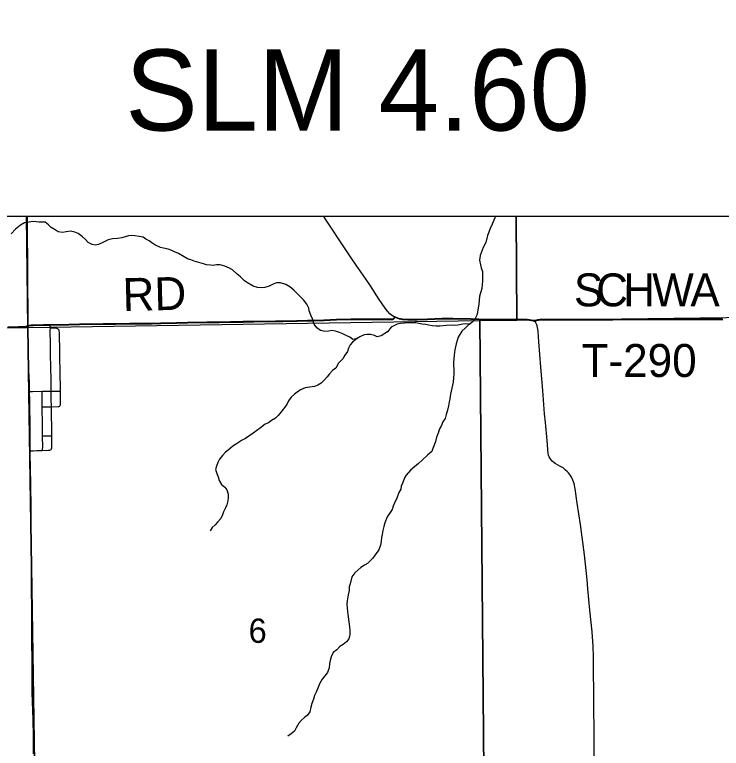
# Model space of a CAD drawing. Extents: x 0 to 34, y 0 to 22.
# Drawn here: x 3.608 to 4.826, y 17.663 to 18.929 of the extents above; entities that cross this region are included whole.
import ezdxf

# ---------------------------------------------------------------- set-up
doc = ezdxf.new("R2010")
doc.units = 0
for name, color, linetype in [('Default', 7, 'Continuous'), ('GM_X_County_Road', 7, 'Continuous'), ('GM_X_Minor_River', 7, 'Continuous'), ('GM_X_Section', 7, 'Continuous'), ('GM_X_Section_Text', 7, 'Continuous'), ('GM_X_Township_Road', 7, 'Continuous'), ('GM_X_Township_Road_Text', 7, 'Continuous'), ('SH_Text', 7, 'Continuous')]:
    doc.layers.add(name, color=color, linetype=linetype)

msp = doc.modelspace()

# ---------------------------------------------------------------- linework, layer by layer
at = {"layer": 'Default'}
for points in [[(4.8287, 18.4036), (4.7759, 18.4035), (4.7231, 18.4033), (4.6858, 18.4035), (4.639, 18.4032), (4.6202, 18.4032), (4.5708, 18.403), (4.5304, 18.403), (4.518, 18.4029), (4.5135, 18.4029), (4.5111, 18.4027), (4.5092, 18.4023), (4.5078, 18.4019), (4.5065, 18.4013), (4.5043, 18.3999), (4.5016, 18.4012), (4.4986, 18.4021), (4.4955, 18.4026), (4.4914, 18.4029), (4.475, 18.4028), (4.4408, 18.4028), (4.4222, 18.403), (4.3942, 18.404), (4.3631, 18.4046), (4.3445, 18.4045), (4.3196, 18.4037), (4.301, 18.4031), (4.2855, 18.4032), (4.2763, 18.4037), (4.2733, 18.4042), (4.2703, 18.4048), (4.2675, 18.4057), (4.2647, 18.4069), (4.2635, 18.4075), (4.262, 18.4054), (4.2613, 18.4045), (4.2607, 18.4041), (4.2596, 18.4037), (4.2574, 18.4035), (4.2496, 18.4034), (4.231, 18.4036), (4.2029, 18.4037), (4.1876, 18.4035), (4.1628, 18.4028), (4.1411, 18.402), (4.1223, 18.4015), (4.1128, 18.4015), (4.0946, 18.4009), (4.0699, 18.4003), (4.0574, 18.4), (4.0452, 18.3998), (4.0201, 18.3994), (4.0016, 18.3993), (3.9799, 18.399), (3.9609, 18.3986), (3.9391, 18.3983), (3.9058, 18.3979), (3.8871, 18.3974), (3.8593, 18.3968), (3.8435, 18.3963), (3.8066, 18.3959), (3.7815, 18.3956), (3.7601, 18.3953), (3.7196, 18.3948), (3.7009, 18.3944), (3.6689, 18.3939), (3.6577, 18.3937), (3.6394, 18.3933), (3.636, 18.3932), (3.6328, 18.3927), (3.6307, 18.3922), (3.6302, 18.392), (3.6272, 18.3911), (3.6239, 18.3906), (3.6146, 18.3902), (3.5959, 18.3898)], [(3.5959, 18.3898), (3.6146, 18.3902), (3.6239, 18.3906), (3.6272, 18.3911), (3.6302, 18.392), (3.6307, 18.3922), (3.6328, 18.3927), (3.636, 18.3932), (3.6394, 18.3933), (3.6577, 18.3937), (3.6689, 18.3939), (3.7009, 18.3944), (3.7196, 18.3948), (3.7601, 18.3953), (3.7815, 18.3956), (3.8066, 18.3959), (3.8435, 18.3963), (3.8593, 18.3968), (3.8871, 18.3974), (3.9058, 18.3979), (3.9391, 18.3983), (3.9609, 18.3986), (3.9799, 18.399), (4.0016, 18.3993), (4.0201, 18.3994), (4.0452, 18.3998), (4.0574, 18.4), (4.0699, 18.4003), (4.0946, 18.4009), (4.1128, 18.4015), (4.1223, 18.4015), (4.1411, 18.402), (4.1628, 18.4028), (4.1876, 18.4035), (4.2029, 18.4037), (4.231, 18.4036), (4.2496, 18.4034), (4.2574, 18.4035), (4.2596, 18.4037), (4.2607, 18.4041), (4.2613, 18.4045), (4.262, 18.4054), (4.2635, 18.4075), (4.2647, 18.4069), (4.2675, 18.4057), (4.2703, 18.4048), (4.2733, 18.4042), (4.2763, 18.4037), (4.2855, 18.4032), (4.301, 18.4031), (4.3196, 18.4037), (4.3445, 18.4045), (4.3631, 18.4046), (4.3942, 18.404), (4.4222, 18.403), (4.4408, 18.4028), (4.475, 18.4028), (4.4914, 18.4029), (4.4955, 18.4026), (4.4986, 18.4021), (4.5016, 18.4012), (4.5043, 18.3999), (4.5065, 18.4013), (4.5078, 18.4019), (4.5092, 18.4023), (4.5111, 18.4027), (4.5135, 18.4029), (4.518, 18.4029), (4.5304, 18.403), (4.5708, 18.403), (4.6202, 18.4032), (4.639, 18.4032), (4.6858, 18.4035), (4.7231, 18.4033), (4.7759, 18.4035), (4.8287, 18.4036)]]:
    msp.add_lwpolyline(points, dxfattribs=at)
at = {"layer": 'GM_X_County_Road'}
for points in [[(3.6309, 18.3916), (3.6308, 18.4178), (3.6306, 18.4613), (3.6302, 18.5078), (3.63, 18.5451), (3.6297, 18.5699), (3.6297, 18.5805)], [(4.2637, 18.4069), (4.2622, 18.4077), (4.2596, 18.4093), (4.2572, 18.4111), (4.2549, 18.413), (4.2507, 18.4174), (4.2467, 18.4224), (4.2362, 18.4377), (4.2211, 18.4609), (4.2125, 18.4738), (4.1968, 18.4968), (4.1881, 18.5095), (4.1778, 18.5249), (4.145, 18.5744), (4.1409, 18.5805)], [(4.5045, 18.3994), (4.5018, 18.4007), (4.4988, 18.4015), (4.4957, 18.402), (4.4916, 18.4024), (4.4752, 18.4023), (4.441, 18.4022), (4.4224, 18.4025), (4.3945, 18.4035), (4.3634, 18.4041), (4.3447, 18.404), (4.3198, 18.4031), (4.3012, 18.4025), (4.2857, 18.4027), (4.2765, 18.4032), (4.2735, 18.4036), (4.2706, 18.4043), (4.2677, 18.4052), (4.2649, 18.4063), (4.2637, 18.4069)], [(4.6069, 17.6467), (4.6071, 17.6716), (4.6069, 17.6964), (4.6065, 17.7306), (4.6064, 17.7586), (4.6061, 17.7975), (4.6057, 17.821), (4.6052, 17.8393), (4.6035, 17.8641), (4.5999, 17.9012), (4.5964, 17.9383), (4.5948, 17.9536), (4.5902, 17.9969), (4.5865, 18.0277), (4.5836, 18.0493), (4.578, 18.0861), (4.5742, 18.1107), (4.5725, 18.12), (4.5705, 18.1256), (4.5694, 18.1284), (4.5681, 18.1312), (4.5665, 18.1337), (4.5645, 18.1363), (4.5629, 18.1383), (4.5607, 18.1407), (4.5578, 18.1433), (4.5534, 18.1469), (4.5481, 18.1501), (4.54, 18.1548), (4.5373, 18.1563), (4.5346, 18.1586), (4.5332, 18.1606), (4.5312, 18.1632), (4.5296, 18.166), (4.5285, 18.1692), (4.528, 18.1722), (4.5272, 18.1789), (4.5259, 18.194), (4.5232, 18.2254), (4.5217, 18.2402), (4.5185, 18.2805), (4.5151, 18.3208), (4.5118, 18.3642), (4.5103, 18.3827), (4.5095, 18.3893), (4.5089, 18.392), (4.5082, 18.3941), (4.5072, 18.3963), (4.5058, 18.3982), (4.5045, 18.3994)], [(3.6344, 18.1766), (3.6342, 18.2128), (3.6337, 18.2626), (3.6334, 18.2787), (3.6333, 18.2936), (3.6323, 18.3153), (3.6313, 18.337), (3.6309, 18.3557), (3.631, 18.3899), (3.6309, 18.3916)], [(3.6404, 17.6536), (3.64, 17.6845), (3.6395, 17.7129), (3.6381, 17.7592), (3.6381, 17.784), (3.6378, 17.8089), (3.6373, 17.8524), (3.6373, 17.8959), (3.637, 17.9456), (3.6369, 17.986), (3.6362, 18.0357), (3.636, 18.0761), (3.6354, 18.1196), (3.6344, 18.1724), (3.6344, 18.1766)]]:
    msp.add_lwpolyline(points, dxfattribs=at)
at = {"layer": 'GM_X_Minor_River'}
for points in [[(4.2016, 18.3723), (4.196, 18.3697), (4.191, 18.3686), (4.1857, 18.3724), (4.1792, 18.3754), (4.1734, 18.3781), (4.1677, 18.3804), (4.1608, 18.3827), (4.1547, 18.3838), (4.1494, 18.3831), (4.1425, 18.3823), (4.1349, 18.3842), (4.1288, 18.3884), (4.1245, 18.3949), (4.1211, 18.404), (4.1184, 18.4105), (4.1157, 18.4177), (4.1149, 18.4226), (4.1115, 18.4295), (4.1061, 18.4367), (4.1012, 18.4413), (4.0954, 18.4474), (4.0889, 18.4538), (4.0824, 18.4595), (4.0751, 18.4633), (4.066, 18.466), (4.0591, 18.466), (4.0538, 18.4637), (4.0469, 18.4603), (4.0393, 18.458), (4.0332, 18.4577), (4.0263, 18.4584), (4.0191, 18.4607), (4.0095, 18.4664), (4.0041, 18.4695), (3.9969, 18.4767), (3.9915, 18.4812), (3.9835, 18.4885), (3.9781, 18.4915), (3.9701, 18.4953), (3.9621, 18.4976), (3.9556, 18.4972), (3.9503, 18.4961), (3.9453, 18.4965), (3.9388, 18.4972), (3.9335, 18.4988), (3.9251, 18.5014), (3.9171, 18.5037), (3.9113, 18.506), (3.906, 18.5075), (3.8999, 18.5113), (3.8903, 18.5167), (3.8834, 18.5197), (3.8785, 18.522), (3.8727, 18.5243), (3.8643, 18.5262), (3.8594, 18.5273), (3.8494, 18.5319), (3.8445, 18.5353), (3.8395, 18.5388), (3.8342, 18.5418), (3.8292, 18.5448), (3.8223, 18.5464), (3.8147, 18.5471), (3.8097, 18.5479), (3.804, 18.5475), (3.7926, 18.5437), (3.7853, 18.543), (3.7765, 18.5422), (3.7689, 18.5407), (3.7609, 18.5365), (3.7525, 18.5327), (3.7468, 18.5312), (3.7411, 18.5323), (3.7346, 18.5361), (3.7296, 18.5411), (3.7239, 18.546), (3.717, 18.5514), (3.7112, 18.5536), (3.704, 18.5552), (3.6964, 18.5544), (3.6903, 18.5533), (3.6826, 18.5544), (3.6773, 18.5579), (3.6708, 18.562), (3.6658, 18.5666), (3.6604, 18.5708), (3.6555, 18.5712), (3.6498, 18.5712), (3.6448, 18.5716), (3.6387, 18.5719), (3.6326, 18.5712), (3.6246, 18.5697), (3.6177, 18.5655), (3.6093, 18.5586), (3.6017, 18.5507)], [(4.4368, 18.5805), (4.4359, 18.5784), (4.431, 18.5673), (4.4279, 18.5601), (4.4256, 18.5536), (4.4234, 18.5479), (4.4203, 18.5358), (4.4158, 18.527), (4.4105, 18.5137), (4.4094, 18.5054), (4.4109, 18.4974), (4.4124, 18.4921), (4.4147, 18.4856), (4.4148, 18.4768), (4.4148, 18.4692), (4.414, 18.4635), (4.4133, 18.4567), (4.4114, 18.451), (4.4091, 18.443), (4.4088, 18.4358), (4.408, 18.4297), (4.4073, 18.4232), (4.4061, 18.4156), (4.4046, 18.4103), (4.4012, 18.4038), (4.3963, 18.3981), (4.3898, 18.3932), (4.3844, 18.3883), (4.3791, 18.3829), (4.3727, 18.3727), (4.3689, 18.3613), (4.3666, 18.3506), (4.3655, 18.3415), (4.3644, 18.3286), (4.3644, 18.3229), (4.3652, 18.3179), (4.3652, 18.3092), (4.3644, 18.3023), (4.3637, 18.2951), (4.3618, 18.2848)], [(4.394, 18.3947), (4.3856, 18.3955), (4.3806, 18.3951), (4.3718, 18.3932), (4.3661, 18.3928), (4.3612, 18.3932), (4.3524, 18.3925), (4.3409, 18.3917), (4.3344, 18.3917), (4.3276, 18.3921), (4.3215, 18.3932), (4.3165, 18.3944), (4.3104, 18.3951), (4.305, 18.3963), (4.2993, 18.397), (4.2925, 18.397), (4.2867, 18.3974), (4.273, 18.3959), (4.2673, 18.3948), (4.257, 18.3898), (4.2505, 18.3815), (4.2398, 18.375), (4.233, 18.3731), (4.228, 18.3754), (4.2215, 18.3773), (4.2158, 18.3769), (4.2105, 18.3766), (4.2028, 18.3731), (4.196, 18.3686), (4.1903, 18.364), (4.1861, 18.3591), (4.1834, 18.3534), (4.1815, 18.3477), (4.1773, 18.3412), (4.1735, 18.3351), (4.1663, 18.3275), (4.1614, 18.3192), (4.156, 18.315), (4.1507, 18.3093), (4.1465, 18.304), (4.1419, 18.299), (4.1362, 18.2933), (4.1305, 18.2895), (4.1248, 18.2876), (4.1168, 18.2861), (4.1088, 18.285), (4.1004, 18.2816), (4.0951, 18.2778), (4.0901, 18.274), (4.0848, 18.269), (4.0798, 18.2626), (4.0772, 18.2561), (4.0673, 18.2439), (4.0623, 18.2371), (4.0574, 18.2329), (4.0509, 18.2287), (4.0456, 18.2245), (4.0399, 18.2223), (4.0315, 18.2162), (4.0254, 18.2116), (4.0193, 18.2067), (4.0056, 18.1976), (3.9991, 18.1941), (3.9903, 18.1884), (3.9838, 18.1843), (3.9762, 18.1774), (3.9713, 18.174), (3.9659, 18.1683), (3.961, 18.1618), (3.958, 18.1561), (3.9557, 18.1501), (3.9538, 18.144), (3.9561, 18.1375), (3.9588, 18.1314), (3.9603, 18.1253), (3.9642, 18.1185), (3.9703, 18.1139), (3.9737, 18.109), (3.976, 18.1018), (3.976, 18.096), (3.9753, 18.0903), (3.9734, 18.0835), (3.9711, 18.0782), (3.9681, 18.0713), (3.9662, 18.066), (3.9632, 18.0599), (3.9578, 18.0535), (3.9536, 18.0485), (3.9483, 18.044), (3.9449, 18.0383)], [(4.3618, 18.2848), (4.3607, 18.2791), (4.3595, 18.2742), (4.358, 18.2662), (4.3573, 18.2609), (4.3561, 18.254), (4.3543, 18.2464), (4.352, 18.2392), (4.3501, 18.232), (4.3459, 18.2263), (4.3433, 18.2191), (4.3402, 18.2141), (4.3379, 18.2069), (4.3353, 18.2), (4.3334, 18.1924), (4.3311, 18.186), (4.3288, 18.1807), (4.327, 18.175), (4.3201, 18.1693), (4.3106, 18.1605), (4.3041, 18.1544), (4.2904, 18.143), (4.2828, 18.1347), (4.2801, 18.1297), (4.2771, 18.1217), (4.2744, 18.1153), (4.2737, 18.1103), (4.2703, 18.1046), (4.2665, 18.0929), (4.2634, 18.0879), (4.2604, 18.0811), (4.2585, 18.075), (4.2543, 18.0685), (4.2501, 18.0624), (4.246, 18.0522), (4.2441, 18.0457), (4.2429, 18.0389), (4.2414, 18.032), (4.2403, 18.0271), (4.2399, 18.0202), (4.2388, 18.0138), (4.2358, 18.0058), (4.2297, 17.9967), (4.2255, 17.991), (4.2164, 17.9818), (4.211, 17.9792), (4.2049, 17.975), (4.1946, 17.9659), (4.1893, 17.959), (4.1863, 17.9469), (4.1848, 17.9416), (4.1844, 17.9355), (4.1829, 17.9282), (4.181, 17.9176), (4.1807, 17.9115), (4.1811, 17.9054), (4.1818, 17.8993), (4.1822, 17.8944), (4.1838, 17.8815), (4.1853, 17.8727), (4.1857, 17.8659), (4.1857, 17.8594), (4.1839, 17.8522), (4.1797, 17.8469), (4.174, 17.8423), (4.1686, 17.8385), (4.1633, 17.8328), (4.1572, 17.8282), (4.1538, 17.821), (4.1519, 17.8146), (4.1508, 17.8089), (4.15, 17.802), (4.1474, 17.794), (4.1428, 17.7879), (4.1382, 17.7822), (4.1337, 17.7746), (4.1318, 17.7697), (4.1276, 17.7598), (4.1246, 17.7541), (4.123, 17.748), (4.1204, 17.7404), (4.1185, 17.734), (4.1166, 17.726), (4.1124, 17.7195), (4.1075, 17.7161), (4.1025, 17.7119), (4.0976, 17.7066), (4.0934, 17.6986), (4.0904, 17.6925), (4.0843, 17.688), (4.0789, 17.6842)]]:
    msp.add_lwpolyline(points, dxfattribs=at)
at = {"layer": 'GM_X_Section'}
for points in [[(4.4724, 18.5805), (4.4738, 18.4018), (5.4223, 18.414), (5.4724, 18.4134), (5.472, 19.4291), (4.4662, 19.4189), (4.4671, 19.2976), (5.3223, 19.2976), (5.3223, 18.5805)], [(3.619, 19.2976), (3.6177, 19.3939), (2.6269, 19.3875), (2.6434, 18.3786), (3.6306, 18.3893), (3.6281, 18.5805), (3.1024, 18.5805), (3.1024, 19.2976)], [(3.6281, 18.5805), (3.6306, 18.3893), (4.4097, 18.4011), (4.4738, 18.4018), (4.4724, 18.5805)], [(4.4738, 18.4018), (5.4223, 18.414), (5.4312, 17.3835), (4.419, 17.3654), (4.4097, 18.4011)], [(3.6306, 18.3893), (4.4097, 18.4011), (4.419, 17.3654), (3.6462, 17.3555), (3.6458, 17.376)], [(2.6434, 18.3786), (3.6306, 18.3893), (3.6458, 17.376), (2.6299, 17.3724), (2.6253, 18.3786)]]:
    msp.add_lwpolyline(points, close=True, dxfattribs=at)
at = {"layer": 'GM_X_Township_Road'}
for points in [[(3.6691, 18.3933), (3.7011, 18.3939), (3.7198, 18.3943), (3.7603, 18.3947), (3.7817, 18.3951), (3.8068, 18.3954), (3.8437, 18.3957), (3.8596, 18.3962), (3.8873, 18.3969), (3.906, 18.3973), (3.9393, 18.3978), (3.9611, 18.3981), (3.9801, 18.3985), (4.0018, 18.3987), (4.0203, 18.3988), (4.0454, 18.3993), (4.0576, 18.3995), (4.0701, 18.3998), (4.0948, 18.4003), (4.113, 18.401), (4.1226, 18.401), (4.1413, 18.4015), (4.163, 18.4023), (4.1878, 18.4029), (4.2031, 18.4031), (4.2312, 18.403), (4.2498, 18.4028), (4.2576, 18.4029), (4.2598, 18.4031), (4.2609, 18.4035), (4.2615, 18.404), (4.2622, 18.4049), (4.2637, 18.4069)], [(4.2637, 18.4069), (4.2649, 18.4063), (4.2677, 18.4052), (4.2706, 18.4043), (4.2735, 18.4036), (4.2765, 18.4032), (4.2857, 18.4027), (4.3012, 18.4025), (4.3198, 18.4031), (4.3447, 18.404), (4.3634, 18.4041), (4.3945, 18.4035), (4.4224, 18.4025), (4.441, 18.4022), (4.4752, 18.4023), (4.4916, 18.4024), (4.4957, 18.402), (4.4988, 18.4015), (4.5018, 18.4007), (4.5045, 18.3994)], [(4.5045, 18.3994), (4.5067, 18.4007), (4.508, 18.4013), (4.5094, 18.4018), (4.5113, 18.4021), (4.5137, 18.4023), (4.5182, 18.4024), (4.5306, 18.4025), (4.571, 18.4025), (4.6204, 18.4026), (4.6392, 18.4026), (4.686, 18.4029), (4.7233, 18.4028), (4.7761, 18.403), (4.8289, 18.4031)], [(3.5961, 18.3892), (3.6148, 18.3897), (3.6241, 18.39), (3.6275, 18.3905), (3.6309, 18.3916)], [(3.6309, 18.3916), (3.633, 18.3921), (3.6362, 18.3927), (3.6396, 18.3928), (3.6579, 18.3932), (3.6691, 18.3933)], [(3.6344, 18.1766), (3.6394, 18.1766), (3.6459, 18.1767), (3.6552, 18.1771), (3.6655, 18.1773), (3.6682, 18.1775), (3.6694, 18.1781), (3.6707, 18.1789), (3.6714, 18.1801), (3.6719, 18.1816), (3.6719, 18.1849), (3.6717, 18.1941), (3.6718, 18.2023), (3.671, 18.2526), (3.6709, 18.2662), (3.6709, 18.2794), (3.6709, 18.2817), (3.6704, 18.3004), (3.67, 18.3192), (3.6696, 18.3442), (3.6694, 18.3598), (3.6692, 18.3847), (3.6694, 18.388), (3.6691, 18.3933)], [(3.6552, 18.2524), (3.6614, 18.2525), (3.6704, 18.2526), (3.671, 18.2526), (3.683, 18.2527), (3.6841, 18.2529), (3.6854, 18.2534), (3.6859, 18.254), (3.6864, 18.2547), (3.6867, 18.2556), (3.6869, 18.2565), (3.6865, 18.2795), (3.6865, 18.2832), (3.686, 18.3113), (3.6855, 18.3394), (3.6855, 18.352), (3.6849, 18.3741), (3.685, 18.3801), (3.6847, 18.3832), (3.6842, 18.3846), (3.6834, 18.3859), (3.6819, 18.3869), (3.6802, 18.3876), (3.6776, 18.3879), (3.6745, 18.3879), (3.6694, 18.388)], [(3.6334, 18.2787), (3.6382, 18.2788), (3.6553, 18.2791), (3.6575, 18.2793), (3.6709, 18.2794), (3.6739, 18.2795), (3.6834, 18.2795), (3.6865, 18.2795)], [(3.6552, 18.1771), (3.6561, 18.182), (3.656, 18.2023), (3.6557, 18.2215), (3.6552, 18.2524), (3.6551, 18.2585), (3.6552, 18.2767), (3.6553, 18.2791)], [(3.656, 18.2023), (3.6614, 18.2023), (3.6689, 18.2023), (3.6718, 18.2023)]]:
    msp.add_lwpolyline(points, dxfattribs=at)
at = {"layer": 'SH_Text'}
msp.add_lwpolyline([(3.1024, 19.2976), (5.3223, 19.2976), (5.3223, 18.5805), (3.1024, 18.5805)], close=True, dxfattribs=at)

# ---------------------------------------------------------------- texts
at = {"layer": 'GM_X_Section_Text'}
msp.add_text('6', height=0.0419, rotation=0, dxfattribs=at).set_placement((4.0112, 17.8451))
at = {"layer": 'GM_X_Township_Road_Text'}
for s, height, rotation, p in [('S', 0.0568, 359.9952, (4.5722, 18.4257)), ('C', 0.0568, 359.9941, (4.6105, 18.4257)), ('H', 0.0568, 359.9952, (4.6572, 18.4257)), ('W', 0.0568, 359.9956, (4.7072, 18.4257)), ('A', 0.0568, 359.9945, (4.773, 18.4257)), ('RD', 0.05682, 1.4271, (3.7945, 18.4174)), ('T-290', 0.05682, 0, (4.5854, 18.3039))]:
    msp.add_text(s, height=height, rotation=rotation, dxfattribs=at).set_placement(p)
at = {"layer": 'SH_Text'}
msp.add_text('SLM 4.60', height=0.14, dxfattribs=at).set_placement((3.7985, 18.7291))

doc.saveas('drawing.dxf')
